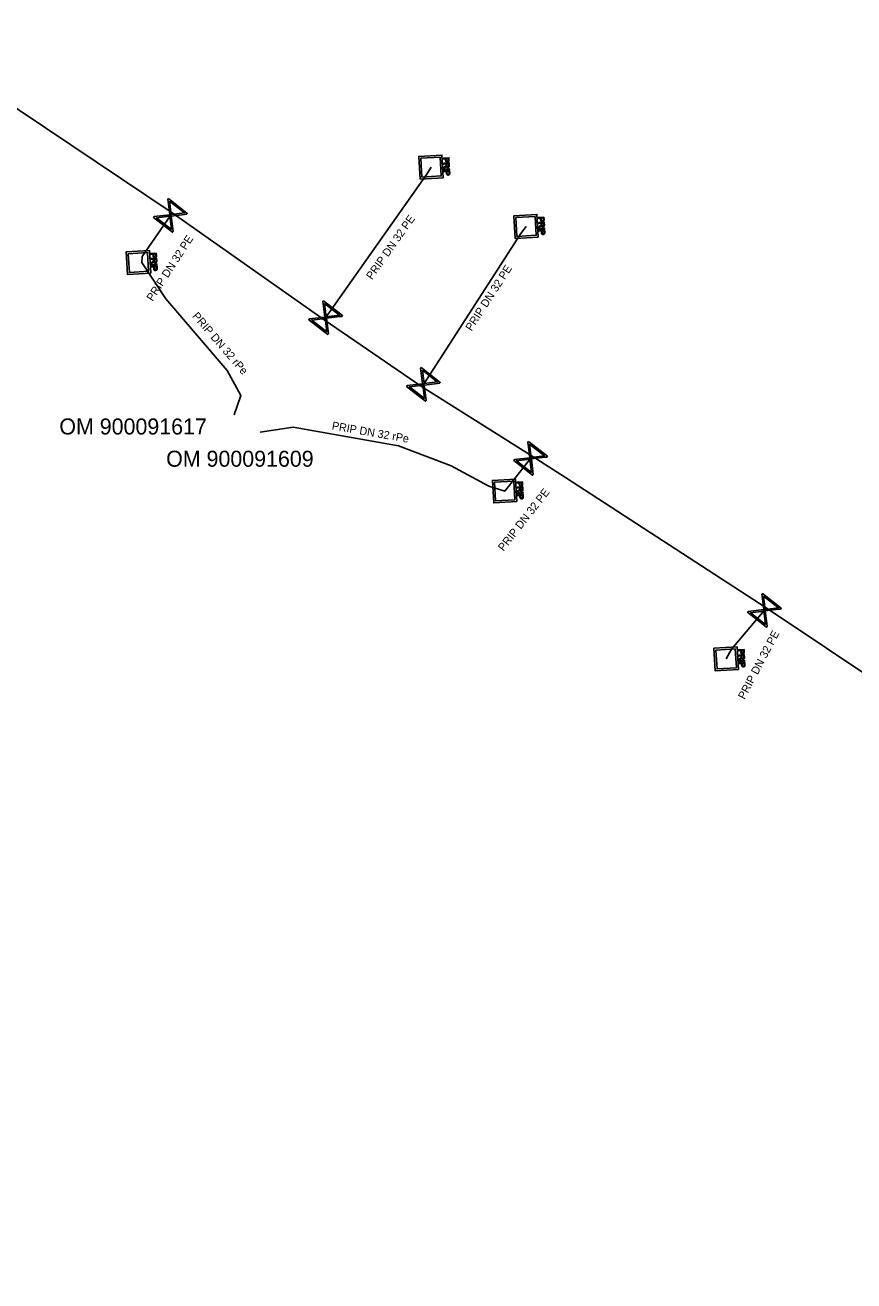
# Model space of a CAD drawing. Extents: x -643544 to -637295, y -1119190 to -1111715.
# Drawn here: x -641968.8 to -641916.9, y -1113568.9 to -1113490.4 of the extents above; entities that cross this region are included whole.
import ezdxf

# ---------------------------------------------------------------- set-up
doc = ezdxf.new("R2010")
doc.units = 0
for name, color, linetype in [('Default', 7, 'Continuous'), ('VP Popis nerozlišený', 7, 'Continuous'), ('VP Popis přípojky', 7, 'Continuous'), ('VP Přípojka', 7, 'Continuous'), ('VP Řad', 7, 'Continuous'), ('VP Šachta', 7, 'Continuous'), ('VP Šoupě', 7, 'Continuous')]:
    doc.layers.add(name, color=color, linetype=linetype)

msp = doc.modelspace()

# ---------------------------------------------------------------- linework, layer by layer
at = {"layer": 'Default'}
for points in [[(-641942.52, -1113499.274), (-641942.488, -1113499.252), (-641942.472, -1113499.237), (-641942.456, -1113499.223), (-641942.45, -1113499.212), (-641942.444, -1113499.2), (-641942.442, -1113499.189), (-641942.44, -1113499.182), (-641942.441, -1113499.163)], [(-641942.239, -1113499.208), (-641942.236, -1113499.255), (-641942.245, -1113499.281), (-641942.253, -1113499.306), (-641942.276, -1113499.323), (-641942.3, -1113499.339), (-641942.329, -1113499.34), (-641942.368, -1113499.343), (-641942.395, -1113499.32), (-641942.422, -1113499.297), (-641942.432, -1113499.246), (-641942.441, -1113499.265), (-641942.449, -1113499.275), (-641942.466, -1113499.297), (-641942.494, -1113499.317)], [(-641942.259, -1113498.864), (-641942.257, -1113498.9), (-641942.26, -1113498.919), (-641942.263, -1113498.945), (-641942.274, -1113498.964), (-641942.285, -1113498.983), (-641942.306, -1113498.995), (-641942.328, -1113499.006), (-641942.355, -1113499.008), (-641942.401, -1113499.011), (-641942.434, -1113498.984), (-641942.466, -1113498.957), (-641942.471, -1113498.881)], [(-641942.429, -1113498.879), (-641942.427, -1113498.925), (-641942.409, -1113498.943), (-641942.39, -1113498.961), (-641942.359, -1113498.959), (-641942.337, -1113498.958), (-641942.322, -1113498.946), (-641942.306, -1113498.934), (-641942.303, -1113498.916), (-641942.3, -1113498.903), (-641942.302, -1113498.87)], [(-641942.398, -1113499.207), (-641942.396, -1113499.24), (-641942.388, -1113499.258), (-641942.381, -1113499.276), (-641942.365, -1113499.284), (-641942.35, -1113499.293), (-641942.332, -1113499.292), (-641942.308, -1113499.29), (-641942.292, -1113499.271), (-641942.277, -1113499.252), (-641942.279, -1113499.211)], [(-641942.214, -1113499.665), (-641942.211, -1113499.7), (-641942.214, -1113499.72), (-641942.217, -1113499.746), (-641942.228, -1113499.765), (-641942.24, -1113499.784), (-641942.261, -1113499.795), (-641942.282, -1113499.807), (-641942.309, -1113499.809), (-641942.355, -1113499.811), (-641942.388, -1113499.785), (-641942.421, -1113499.758), (-641942.425, -1113499.682)], [(-641942.384, -1113499.68), (-641942.381, -1113499.726), (-641942.363, -1113499.744), (-641942.345, -1113499.762), (-641942.313, -1113499.76), (-641942.291, -1113499.759), (-641942.276, -1113499.747), (-641942.261, -1113499.735), (-641942.257, -1113499.716), (-641942.254, -1113499.704), (-641942.256, -1113499.671)], [(-641936.319, -1113502.574), (-641936.317, -1113502.61), (-641936.32, -1113502.629), (-641936.323, -1113502.655), (-641936.334, -1113502.674), (-641936.345, -1113502.693), (-641936.366, -1113502.705), (-641936.388, -1113502.716), (-641936.415, -1113502.718), (-641936.461, -1113502.721), (-641936.494, -1113502.694), (-641936.526, -1113502.667), (-641936.531, -1113502.591)], [(-641936.489, -1113502.589), (-641936.487, -1113502.635), (-641936.469, -1113502.653), (-641936.45, -1113502.671), (-641936.419, -1113502.669), (-641936.397, -1113502.668), (-641936.382, -1113502.656), (-641936.366, -1113502.644), (-641936.363, -1113502.626), (-641936.36, -1113502.613), (-641936.362, -1113502.58)], [(-641936.58, -1113502.984), (-641936.548, -1113502.962), (-641936.532, -1113502.947), (-641936.516, -1113502.933), (-641936.51, -1113502.922), (-641936.504, -1113502.91), (-641936.502, -1113502.899), (-641936.5, -1113502.892), (-641936.501, -1113502.873)], [(-641936.299, -1113502.918), (-641936.296, -1113502.965), (-641936.305, -1113502.991), (-641936.313, -1113503.016), (-641936.336, -1113503.033), (-641936.36, -1113503.049), (-641936.389, -1113503.05), (-641936.428, -1113503.053), (-641936.455, -1113503.03), (-641936.482, -1113503.007), (-641936.492, -1113502.956), (-641936.501, -1113502.975), (-641936.509, -1113502.985), (-641936.526, -1113503.007), (-641936.554, -1113503.027)], [(-641936.274, -1113503.375), (-641936.271, -1113503.41), (-641936.274, -1113503.43), (-641936.277, -1113503.456), (-641936.288, -1113503.475), (-641936.3, -1113503.494), (-641936.321, -1113503.505), (-641936.342, -1113503.517), (-641936.369, -1113503.519), (-641936.415, -1113503.521), (-641936.448, -1113503.495), (-641936.481, -1113503.468), (-641936.485, -1113503.392)], [(-641936.458, -1113502.917), (-641936.456, -1113502.95), (-641936.448, -1113502.968), (-641936.441, -1113502.986), (-641936.425, -1113502.994), (-641936.41, -1113503.003), (-641936.392, -1113503.002), (-641936.368, -1113503), (-641936.352, -1113502.981), (-641936.337, -1113502.962), (-641936.339, -1113502.921)], [(-641936.444, -1113503.39), (-641936.441, -1113503.436), (-641936.423, -1113503.454), (-641936.405, -1113503.472), (-641936.373, -1113503.47), (-641936.351, -1113503.469), (-641936.336, -1113503.457), (-641936.321, -1113503.445), (-641936.317, -1113503.426), (-641936.314, -1113503.414), (-641936.316, -1113503.381)], [(-641960.549, -1113504.824), (-641960.547, -1113504.86), (-641960.55, -1113504.879), (-641960.553, -1113504.905), (-641960.564, -1113504.924), (-641960.575, -1113504.943), (-641960.596, -1113504.955), (-641960.618, -1113504.966), (-641960.645, -1113504.968), (-641960.691, -1113504.971), (-641960.724, -1113504.944), (-641960.756, -1113504.917), (-641960.761, -1113504.841)], [(-641960.719, -1113504.839), (-641960.717, -1113504.885), (-641960.699, -1113504.903), (-641960.68, -1113504.921), (-641960.649, -1113504.919), (-641960.627, -1113504.918), (-641960.612, -1113504.906), (-641960.596, -1113504.894), (-641960.593, -1113504.876), (-641960.59, -1113504.863), (-641960.592, -1113504.83)], [(-641960.81, -1113505.234), (-641960.778, -1113505.212), (-641960.762, -1113505.197), (-641960.746, -1113505.183), (-641960.74, -1113505.172), (-641960.734, -1113505.16), (-641960.732, -1113505.149), (-641960.73, -1113505.142), (-641960.731, -1113505.123)], [(-641960.529, -1113505.168), (-641960.526, -1113505.215), (-641960.535, -1113505.241), (-641960.543, -1113505.266), (-641960.566, -1113505.283), (-641960.59, -1113505.299), (-641960.619, -1113505.3), (-641960.658, -1113505.303), (-641960.685, -1113505.28), (-641960.712, -1113505.257), (-641960.722, -1113505.206), (-641960.731, -1113505.225), (-641960.739, -1113505.235), (-641960.756, -1113505.257), (-641960.784, -1113505.277)], [(-641960.504, -1113505.625), (-641960.501, -1113505.66), (-641960.504, -1113505.68), (-641960.507, -1113505.706), (-641960.518, -1113505.725), (-641960.53, -1113505.744), (-641960.551, -1113505.755), (-641960.572, -1113505.767), (-641960.599, -1113505.769), (-641960.645, -1113505.771), (-641960.678, -1113505.745), (-641960.711, -1113505.718), (-641960.715, -1113505.642)], [(-641960.688, -1113505.167), (-641960.686, -1113505.2), (-641960.678, -1113505.218), (-641960.671, -1113505.236), (-641960.655, -1113505.244), (-641960.64, -1113505.253), (-641960.622, -1113505.252), (-641960.598, -1113505.25), (-641960.582, -1113505.231), (-641960.567, -1113505.212), (-641960.569, -1113505.171)], [(-641960.674, -1113505.64), (-641960.671, -1113505.686), (-641960.653, -1113505.704), (-641960.635, -1113505.722), (-641960.603, -1113505.72), (-641960.581, -1113505.719), (-641960.566, -1113505.707), (-641960.551, -1113505.695), (-641960.547, -1113505.676), (-641960.544, -1113505.664), (-641960.546, -1113505.631)], [(-641937.92, -1113519.514), (-641937.888, -1113519.491), (-641937.872, -1113519.476), (-641937.856, -1113519.462), (-641937.85, -1113519.451), (-641937.844, -1113519.439), (-641937.842, -1113519.428), (-641937.84, -1113519.421), (-641937.841, -1113519.403)], [(-641937.639, -1113519.447), (-641937.636, -1113519.495), (-641937.645, -1113519.52), (-641937.653, -1113519.546), (-641937.676, -1113519.562), (-641937.7, -1113519.578), (-641937.729, -1113519.579), (-641937.768, -1113519.582), (-641937.795, -1113519.559), (-641937.822, -1113519.536), (-641937.832, -1113519.485), (-641937.841, -1113519.504), (-641937.849, -1113519.514), (-641937.866, -1113519.536), (-641937.894, -1113519.556)], [(-641937.659, -1113519.103), (-641937.657, -1113519.139), (-641937.66, -1113519.158), (-641937.663, -1113519.184), (-641937.674, -1113519.203), (-641937.685, -1113519.222), (-641937.706, -1113519.234), (-641937.728, -1113519.246), (-641937.755, -1113519.247), (-641937.801, -1113519.25), (-641937.834, -1113519.223), (-641937.866, -1113519.196), (-641937.871, -1113519.121)], [(-641937.829, -1113519.118), (-641937.827, -1113519.164), (-641937.809, -1113519.182), (-641937.79, -1113519.2), (-641937.759, -1113519.198), (-641937.737, -1113519.197), (-641937.722, -1113519.185), (-641937.706, -1113519.173), (-641937.703, -1113519.155), (-641937.7, -1113519.142), (-641937.702, -1113519.109)], [(-641937.798, -1113519.446), (-641937.796, -1113519.479), (-641937.788, -1113519.497), (-641937.781, -1113519.515), (-641937.765, -1113519.523), (-641937.75, -1113519.532), (-641937.732, -1113519.531), (-641937.708, -1113519.529), (-641937.692, -1113519.51), (-641937.677, -1113519.491), (-641937.679, -1113519.451)], [(-641937.614, -1113519.904), (-641937.611, -1113519.939), (-641937.614, -1113519.959), (-641937.617, -1113519.985), (-641937.628, -1113520.004), (-641937.64, -1113520.023), (-641937.661, -1113520.035), (-641937.682, -1113520.046), (-641937.709, -1113520.048), (-641937.755, -1113520.05), (-641937.788, -1113520.024), (-641937.821, -1113519.997), (-641937.825, -1113519.921)], [(-641937.784, -1113519.919), (-641937.781, -1113519.965), (-641937.763, -1113519.983), (-641937.745, -1113520.001), (-641937.713, -1113519.999), (-641937.691, -1113519.998), (-641937.676, -1113519.986), (-641937.661, -1113519.974), (-641937.657, -1113519.955), (-641937.654, -1113519.943), (-641937.656, -1113519.91)], [(-641924.07, -1113530.004), (-641924.038, -1113529.982), (-641924.022, -1113529.967), (-641924.006, -1113529.953), (-641924, -1113529.942), (-641923.994, -1113529.93), (-641923.992, -1113529.919), (-641923.99, -1113529.912), (-641923.991, -1113529.893)], [(-641923.789, -1113529.938), (-641923.786, -1113529.985), (-641923.795, -1113530.011), (-641923.803, -1113530.036), (-641923.826, -1113530.053), (-641923.85, -1113530.069), (-641923.879, -1113530.07), (-641923.918, -1113530.073), (-641923.945, -1113530.05), (-641923.972, -1113530.027), (-641923.982, -1113529.976), (-641923.991, -1113529.995), (-641923.999, -1113530.005), (-641924.016, -1113530.027), (-641924.044, -1113530.047)], [(-641923.809, -1113529.594), (-641923.807, -1113529.63), (-641923.81, -1113529.649), (-641923.813, -1113529.675), (-641923.824, -1113529.694), (-641923.835, -1113529.713), (-641923.856, -1113529.725), (-641923.878, -1113529.736), (-641923.905, -1113529.738), (-641923.951, -1113529.741), (-641923.984, -1113529.714), (-641924.016, -1113529.687), (-641924.021, -1113529.611)], [(-641923.979, -1113529.609), (-641923.977, -1113529.655), (-641923.959, -1113529.673), (-641923.94, -1113529.691), (-641923.909, -1113529.689), (-641923.887, -1113529.688), (-641923.872, -1113529.676), (-641923.856, -1113529.664), (-641923.853, -1113529.646), (-641923.85, -1113529.633), (-641923.852, -1113529.6)], [(-641923.948, -1113529.937), (-641923.946, -1113529.97), (-641923.938, -1113529.988), (-641923.931, -1113530.006), (-641923.915, -1113530.014), (-641923.9, -1113530.023), (-641923.882, -1113530.022), (-641923.858, -1113530.02), (-641923.842, -1113530.001), (-641923.827, -1113529.982), (-641923.829, -1113529.941)], [(-641923.764, -1113530.395), (-641923.761, -1113530.43), (-641923.764, -1113530.45), (-641923.767, -1113530.476), (-641923.778, -1113530.495), (-641923.79, -1113530.514), (-641923.811, -1113530.525), (-641923.832, -1113530.537), (-641923.859, -1113530.539), (-641923.905, -1113530.541), (-641923.938, -1113530.515), (-641923.971, -1113530.488), (-641923.975, -1113530.412)], [(-641923.934, -1113530.41), (-641923.931, -1113530.456), (-641923.913, -1113530.474), (-641923.895, -1113530.492), (-641923.863, -1113530.49), (-641923.841, -1113530.489), (-641923.826, -1113530.477), (-641923.811, -1113530.465), (-641923.807, -1113530.446), (-641923.804, -1113530.434), (-641923.806, -1113530.401)]]:
    msp.add_open_spline(points, degree=3, dxfattribs=at)
at = {"layer": 'VP Přípojka'}
for points in [[(-641950.07, -1113508.85), (-641949.97, -1113508.72), (-641943.64, -1113499.75), (-641943.38, -1113499.31)], [(-641955.69, -1113514.78), (-641955.269, -1113513.59), (-641956.12, -1113512.01), (-641959.969, -1113507.54), (-641961.47, -1113505.28), (-641961.43, -1113504.9), (-641959.67, -1113502.33), (-641959.57, -1113502.17)], [(-641943.97, -1113513.02), (-641943.86, -1113512.89), (-641937.77, -1113503.45), (-641937.44, -1113503.02)], [(-641954.069, -1113515.88), (-641952.01, -1113515.56), (-641945.42, -1113516.72), (-641942.12, -1113517.97), (-641939.77, -1113519.24), (-641938.77, -1113519.56), (-641937.16, -1113517.51), (-641937.06, -1113517.37)], [(-641924.93, -1113530.04), (-641924.61, -1113529.43), (-641922.54, -1113527), (-641922.44, -1113526.85)]]:
    msp.add_lwpolyline(points, dxfattribs=at)
at = {"layer": 'VP Řad'}
msp.add_lwpolyline([(-641857.82, -1113579.43), (-641862.85, -1113574.5), (-641870.19, -1113567.49), (-641878.25, -1113559.43), (-641879.94, -1113557.92), (-641885.11, -1113553.34), (-641893.02, -1113547.12), (-641901.21, -1113541.4), (-641911.54, -1113534.19), (-641914.89, -1113531.89), (-641922.44, -1113526.85), (-641927.665, -1113523.455), (-641934.975, -1113518.715), (-641937.06, -1113517.37), (-641943.97, -1113513.02), (-641950.07, -1113508.85), (-641959.57, -1113502.17), (-641977.07, -1113490.44)], dxfattribs=at)
at = {"layer": 'VP Šachta'}
for points in [[(-641942.617, -1113499.973), (-641944.066, -1113500.058), (-641944.149, -1113498.647), (-641942.7, -1113498.562), (-641942.617, -1113499.973)], [(-641942.816, -1113498.69), (-641944.019, -1113498.76), (-641943.95, -1113499.93), (-641942.747, -1113499.86), (-641942.816, -1113498.69)], [(-641942.625, -1113498.751), (-641942.267, -1113498.73), (-641942.259, -1113498.864)], [(-641942.471, -1113498.881), (-641942.476, -1113498.789), (-641942.622, -1113498.797), (-641942.625, -1113498.751)], [(-641942.607, -1113499.07), (-641942.248, -1113499.049), (-641942.239, -1113499.208)], [(-641942.441, -1113499.163), (-641942.444, -1113499.109), (-641942.604, -1113499.118), (-641942.607, -1113499.07)], [(-641942.494, -1113499.317), (-641942.588, -1113499.385), (-641942.592, -1113499.325), (-641942.52, -1113499.274)], [(-641942.587, -1113499.434), (-641942.228, -1113499.413), (-641942.226, -1113499.459), (-641942.584, -1113499.48), (-641942.587, -1113499.434)], [(-641942.302, -1113498.87), (-641942.307, -1113498.779), (-641942.435, -1113498.786)], [(-641942.435, -1113498.786), (-641942.429, -1113498.879)], [(-641942.279, -1113499.211), (-641942.286, -1113499.099), (-641942.404, -1113499.106)], [(-641942.404, -1113499.106), (-641942.398, -1113499.207)], [(-641942.58, -1113499.552), (-641942.221, -1113499.531), (-641942.214, -1113499.665)], [(-641942.425, -1113499.682), (-641942.431, -1113499.59), (-641942.577, -1113499.598), (-641942.58, -1113499.552)], [(-641942.256, -1113499.671), (-641942.261, -1113499.58), (-641942.389, -1113499.587)], [(-641942.389, -1113499.587), (-641942.384, -1113499.68)], [(-641936.677, -1113503.683), (-641938.126, -1113503.768), (-641938.209, -1113502.357), (-641936.76, -1113502.272), (-641936.677, -1113503.683)], [(-641936.876, -1113502.4), (-641938.079, -1113502.47), (-641938.01, -1113503.64), (-641936.807, -1113503.57), (-641936.876, -1113502.4)], [(-641936.685, -1113502.461), (-641936.327, -1113502.44), (-641936.319, -1113502.574)], [(-641936.531, -1113502.591), (-641936.536, -1113502.499), (-641936.682, -1113502.507), (-641936.685, -1113502.461)], [(-641936.362, -1113502.58), (-641936.367, -1113502.489), (-641936.495, -1113502.496)], [(-641936.495, -1113502.496), (-641936.489, -1113502.589)], [(-641936.667, -1113502.78), (-641936.308, -1113502.759), (-641936.299, -1113502.918)], [(-641936.501, -1113502.873), (-641936.504, -1113502.819), (-641936.664, -1113502.828), (-641936.667, -1113502.78)], [(-641936.554, -1113503.027), (-641936.648, -1113503.095), (-641936.652, -1113503.035), (-641936.58, -1113502.984)], [(-641936.647, -1113503.144), (-641936.288, -1113503.123), (-641936.286, -1113503.169), (-641936.644, -1113503.19), (-641936.647, -1113503.144)], [(-641936.64, -1113503.262), (-641936.281, -1113503.241), (-641936.274, -1113503.375)], [(-641936.485, -1113503.392), (-641936.491, -1113503.3), (-641936.637, -1113503.308), (-641936.64, -1113503.262)], [(-641936.339, -1113502.921), (-641936.346, -1113502.809), (-641936.464, -1113502.816)], [(-641936.464, -1113502.816), (-641936.458, -1113502.917)], [(-641936.316, -1113503.381), (-641936.321, -1113503.29), (-641936.449, -1113503.297)], [(-641936.449, -1113503.297), (-641936.444, -1113503.39)], [(-641960.907, -1113505.933), (-641962.356, -1113506.018), (-641962.439, -1113504.607), (-641960.99, -1113504.522), (-641960.907, -1113505.933)], [(-641961.106, -1113504.65), (-641962.309, -1113504.72), (-641962.24, -1113505.89), (-641961.037, -1113505.82), (-641961.106, -1113504.65)], [(-641960.915, -1113504.711), (-641960.557, -1113504.69), (-641960.549, -1113504.824)], [(-641960.761, -1113504.841), (-641960.766, -1113504.749), (-641960.912, -1113504.757), (-641960.915, -1113504.711)], [(-641960.592, -1113504.83), (-641960.597, -1113504.739), (-641960.725, -1113504.746)], [(-641960.725, -1113504.746), (-641960.719, -1113504.839)], [(-641960.897, -1113505.03), (-641960.538, -1113505.009), (-641960.529, -1113505.168)], [(-641960.731, -1113505.123), (-641960.734, -1113505.069), (-641960.894, -1113505.078), (-641960.897, -1113505.03)], [(-641960.784, -1113505.277), (-641960.878, -1113505.345), (-641960.882, -1113505.285), (-641960.81, -1113505.234)], [(-641960.877, -1113505.394), (-641960.518, -1113505.373), (-641960.516, -1113505.419), (-641960.874, -1113505.44), (-641960.877, -1113505.394)], [(-641960.87, -1113505.512), (-641960.511, -1113505.491), (-641960.504, -1113505.625)], [(-641960.715, -1113505.642), (-641960.721, -1113505.55), (-641960.867, -1113505.558), (-641960.87, -1113505.512)], [(-641960.569, -1113505.171), (-641960.576, -1113505.059), (-641960.694, -1113505.066)], [(-641960.694, -1113505.066), (-641960.688, -1113505.167)], [(-641960.546, -1113505.631), (-641960.551, -1113505.54), (-641960.679, -1113505.547)], [(-641960.679, -1113505.547), (-641960.674, -1113505.64)], [(-641938.017, -1113520.213), (-641939.466, -1113520.297), (-641939.549, -1113518.886), (-641938.1, -1113518.801), (-641938.017, -1113520.213)], [(-641938.216, -1113518.929), (-641939.419, -1113519), (-641939.35, -1113520.169), (-641938.147, -1113520.099), (-641938.216, -1113518.929)], [(-641938.025, -1113518.99), (-641937.667, -1113518.969), (-641937.659, -1113519.103)], [(-641937.871, -1113519.121), (-641937.876, -1113519.028), (-641938.022, -1113519.037), (-641938.025, -1113518.99)], [(-641937.702, -1113519.109), (-641937.707, -1113519.018), (-641937.835, -1113519.026)], [(-641937.835, -1113519.026), (-641937.829, -1113519.118)], [(-641938.007, -1113519.309), (-641937.648, -1113519.289), (-641937.639, -1113519.447)], [(-641937.841, -1113519.403), (-641937.844, -1113519.348), (-641938.004, -1113519.357), (-641938.007, -1113519.309)], [(-641937.894, -1113519.556), (-641937.988, -1113519.624), (-641937.992, -1113519.564), (-641937.92, -1113519.514)], [(-641937.987, -1113519.673), (-641937.628, -1113519.652), (-641937.626, -1113519.698), (-641937.984, -1113519.719), (-641937.987, -1113519.673)], [(-641937.98, -1113519.791), (-641937.621, -1113519.77), (-641937.614, -1113519.904)], [(-641937.825, -1113519.921), (-641937.831, -1113519.829), (-641937.977, -1113519.837), (-641937.98, -1113519.791)], [(-641937.679, -1113519.451), (-641937.686, -1113519.338), (-641937.804, -1113519.345)], [(-641937.804, -1113519.345), (-641937.798, -1113519.446)], [(-641937.656, -1113519.91), (-641937.661, -1113519.819), (-641937.789, -1113519.826)], [(-641937.789, -1113519.826), (-641937.784, -1113519.919)], [(-641924.167, -1113530.703), (-641925.616, -1113530.788), (-641925.699, -1113529.377), (-641924.25, -1113529.292), (-641924.167, -1113530.703)], [(-641924.366, -1113529.42), (-641925.569, -1113529.49), (-641925.5, -1113530.66), (-641924.297, -1113530.59), (-641924.366, -1113529.42)], [(-641924.175, -1113529.481), (-641923.817, -1113529.46), (-641923.809, -1113529.594)], [(-641924.021, -1113529.611), (-641924.026, -1113529.519), (-641924.172, -1113529.527), (-641924.175, -1113529.481)], [(-641924.157, -1113529.8), (-641923.798, -1113529.779), (-641923.789, -1113529.938)], [(-641923.991, -1113529.893), (-641923.994, -1113529.839), (-641924.154, -1113529.848), (-641924.157, -1113529.8)], [(-641924.044, -1113530.047), (-641924.138, -1113530.115), (-641924.142, -1113530.055), (-641924.07, -1113530.004)], [(-641923.852, -1113529.6), (-641923.857, -1113529.509), (-641923.985, -1113529.516)], [(-641923.985, -1113529.516), (-641923.979, -1113529.609)], [(-641923.829, -1113529.941), (-641923.836, -1113529.829), (-641923.954, -1113529.836)], [(-641923.954, -1113529.836), (-641923.948, -1113529.937)], [(-641924.137, -1113530.164), (-641923.778, -1113530.143), (-641923.776, -1113530.189), (-641924.134, -1113530.21), (-641924.137, -1113530.164)], [(-641924.13, -1113530.282), (-641923.771, -1113530.261), (-641923.764, -1113530.395)], [(-641923.975, -1113530.412), (-641923.981, -1113530.32), (-641924.127, -1113530.328), (-641924.13, -1113530.282)], [(-641923.806, -1113530.401), (-641923.811, -1113530.31), (-641923.939, -1113530.317)], [(-641923.939, -1113530.317), (-641923.934, -1113530.41)]]:
    msp.add_lwpolyline(points, dxfattribs=at)
at = {"layer": 'VP Šoupě'}
for points in [[(-641959.799, -1113501.277), (-641958.617, -1113502.201), (-641958.658, -1113502.253), (-641958.786, -1113502.264), (-641959.619, -1113502.368), (-641959.5, -1113503.331), (-641959.541, -1113503.383), (-641960.723, -1113502.459), (-641960.682, -1113502.407), (-641959.718, -1113502.291), (-641959.821, -1113501.457), (-641959.84, -1113501.329), (-641959.799, -1113501.277)], [(-641959.733, -1113501.448), (-641959.63, -1113502.28), (-641958.8, -1113502.177), (-641959.733, -1113501.448)], [(-641959.603, -1113503.215), (-641959.707, -1113502.378), (-641960.542, -1113502.482), (-641959.603, -1113503.215)], [(-641950.099, -1113507.667), (-641948.917, -1113508.591), (-641948.958, -1113508.643), (-641949.086, -1113508.654), (-641949.919, -1113508.758), (-641949.8, -1113509.721), (-641949.841, -1113509.773), (-641951.023, -1113508.849), (-641950.982, -1113508.797), (-641950.018, -1113508.681), (-641950.121, -1113507.847), (-641950.14, -1113507.719), (-641950.099, -1113507.667)], [(-641950.033, -1113507.838), (-641949.93, -1113508.67), (-641949.1, -1113508.567), (-641950.033, -1113507.838)], [(-641949.903, -1113509.605), (-641950.007, -1113508.768), (-641950.842, -1113508.872), (-641949.903, -1113509.605)], [(-641943.989, -1113511.837), (-641942.807, -1113512.761), (-641942.848, -1113512.813), (-641942.976, -1113512.824), (-641943.809, -1113512.928), (-641943.69, -1113513.891), (-641943.731, -1113513.943), (-641944.913, -1113513.019), (-641944.872, -1113512.967), (-641943.908, -1113512.851), (-641944.011, -1113512.017), (-641944.03, -1113511.889), (-641943.989, -1113511.837)], [(-641943.923, -1113512.008), (-641943.82, -1113512.84), (-641942.99, -1113512.737), (-641943.923, -1113512.008)], [(-641943.793, -1113513.775), (-641943.897, -1113512.938), (-641944.732, -1113513.042), (-641943.793, -1113513.775)], [(-641937.289, -1113516.457), (-641936.107, -1113517.381), (-641936.148, -1113517.433), (-641936.276, -1113517.444), (-641937.109, -1113517.548), (-641936.99, -1113518.511), (-641937.031, -1113518.563), (-641938.213, -1113517.639), (-641938.172, -1113517.587), (-641937.208, -1113517.471), (-641937.311, -1113516.637), (-641937.33, -1113516.509), (-641937.289, -1113516.457)], [(-641937.223, -1113516.628), (-641937.12, -1113517.46), (-641936.29, -1113517.357), (-641937.223, -1113516.628)], [(-641937.093, -1113518.395), (-641937.197, -1113517.558), (-641938.032, -1113517.662), (-641937.093, -1113518.395)], [(-641922.669, -1113525.947), (-641921.487, -1113526.871), (-641921.528, -1113526.923), (-641921.656, -1113526.934), (-641922.489, -1113527.038), (-641922.37, -1113528.001), (-641922.411, -1113528.053), (-641923.593, -1113527.129), (-641923.552, -1113527.077), (-641922.588, -1113526.961), (-641922.691, -1113526.127), (-641922.71, -1113525.999), (-641922.669, -1113525.947)], [(-641922.603, -1113526.118), (-641922.5, -1113526.95), (-641921.67, -1113526.847), (-641922.603, -1113526.118)], [(-641922.473, -1113527.885), (-641922.577, -1113527.048), (-641923.412, -1113527.152), (-641922.473, -1113527.885)]]:
    msp.add_lwpolyline(points, dxfattribs=at)

# ---------------------------------------------------------------- texts
at = {"layer": 'VP Popis nerozlišený'}
for s, p in [('OM 900091617', (-641966.615, -1113516.016)), ('OM 900091609', (-641959.939, -1113518.032))]:
    msp.add_text(s, height=1, dxfattribs=at).set_placement(p)
at = {"layer": 'VP Popis přípojky'}
for s, rotation, p in [('PRIP DN 32 PE', 54.78993, (-641947.073, -1113506.385)), ('PRIP DN 32 PE', 57.0306, (-641960.787, -1113507.736)), ('PRIP DN 32 PE', 57.17284, (-641940.851, -1113509.595)), ('PRIP DN 32 rPe', 310.73101, (-641958.336, -1113508.639)), ('PRIP DN 32 rPe', 350.01682, (-641949.608, -1113515.695)), ('PRIP DN 32 PE', 51.98106, (-641938.846, -1113523.352)), ('PRIP DN 32 PE', 62.31894, (-641923.78, -1113532.611))]:
    msp.add_text(s, height=0.5, rotation=rotation, dxfattribs=at).set_placement(p)

doc.saveas('drawing.dxf')
